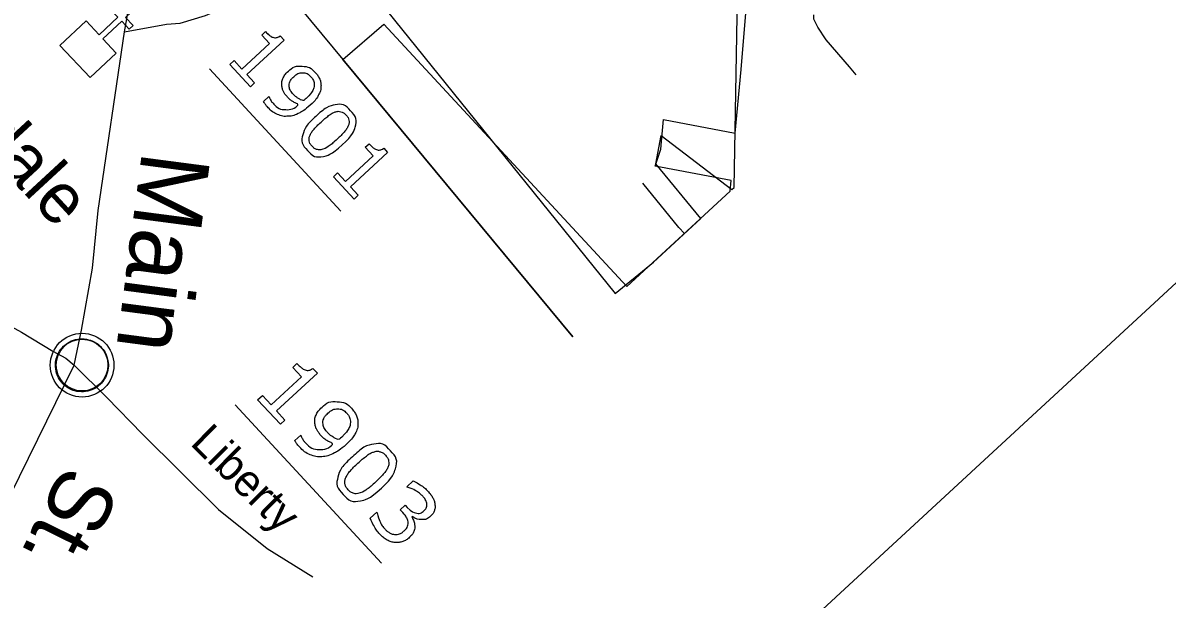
# Model space of a CAD drawing. Extents: x 1695041 to 1706254, y 786537 to 798223.
# Drawn here: x 1703274.6 to 1703431.2, y 796468.6 to 796547.5 of the extents above; entities that cross this region are included whole.
import ezdxf

# ---------------------------------------------------------------- set-up
doc = ezdxf.new("R2010")
doc.units = 0
for name, color, linetype in [('Default', 7, 'Continuous'), ('Old_Level_29', 7, 'Continuous'), ('Old_Level_32', 7, 'Continuous')]:
    doc.layers.add(name, color=color, linetype=linetype)

msp = doc.modelspace()

# ---------------------------------------------------------------- linework, layer by layer
at = {"layer": 'Default'}
for p, q in [((1703300.12, 796541.16), (1703318.09, 796521.69)), ((1703357.25, 796511.38), (1703371.39, 796524.43)), ((1703357.25, 796511.38), (1703371.39, 796524.43)), ((1703371.64, 796524.66), (1703371.94, 796524.93)), ((1703371.64, 796524.66), (1703371.94, 796524.93)), ((1703360.9, 796514.74), (1703367.37, 796520.71)), ((1703360.9, 796514.74), (1703367.37, 796520.71)), ((1703303.65, 796495.22), (1703323.66, 796473.54))]:
    msp.add_line(p, q, dxfattribs=at)
for points in [[(1703207.65, 797564.73), (1702636.99, 797037.98), (1703265.12, 796357.5), (1703835.77, 796884.26)], [(1702807.76, 797162.38), (1703001.1, 796924.8), (1703349.84, 796504.53)], [(1702807.76, 797162.38), (1703001.1, 796924.8), (1703349.84, 796504.53)], [(1703371.39, 796524.43), (1703371.52, 796525.89), (1703361.13, 796527.87), (1703361.9, 796530.18), (1703362.01, 796531.24), (1703362.28, 796534.24), (1703372.1, 796532.36), (1703372.88, 796541.09), (1703375.01, 796566.38), (1703386.35, 796574.51), (1703405.54, 796588.27), (1703399.28, 796595.84), (1703390.32, 796606.91), (1703386.08, 796612.13)], [(1703371.39, 796524.43), (1703371.52, 796525.89), (1703361.13, 796527.87), (1703361.9, 796530.18), (1703362.01, 796531.24), (1703362.28, 796534.24), (1703372.1, 796532.36), (1703372.88, 796541.09), (1703375.01, 796566.38), (1703386.35, 796574.51), (1703405.54, 796588.27), (1703399.28, 796595.84), (1703390.32, 796606.91), (1703386.08, 796612.13)], [(1703371.94, 796524.93), (1703372.66, 796566.64), (1703383.15, 796574.17)], [(1703371.94, 796524.93), (1703372.66, 796566.64), (1703383.15, 796574.17)], [(1703311.01, 796570.02), (1703306.15, 796565.77), (1703312, 796559.82), (1703306.76, 796554.78), (1703310.43, 796550.3), (1703318.36, 796556.64), (1703355.63, 796510.46), (1703360.9, 796514.74)], [(1703311.01, 796570.02), (1703306.15, 796565.77), (1703312, 796559.82), (1703306.76, 796554.78), (1703310.43, 796550.3), (1703318.36, 796556.64), (1703355.63, 796510.46), (1703360.9, 796514.74)], [(1703388.63, 796540.34), (1703387.75, 796541.43), (1703384.53, 796545.16), (1703383.38, 796546.89), (1703382.84, 796547.96), (1703382.84, 796548.56)], [(1703305.72, 796538.71), (1703302.9, 796541.77), (1703303.48, 796542.3), (1703304.56, 796541.13), (1703308.35, 796544.62), (1703307.26, 796545.8), (1703307.78, 796546.27)], [(1703349.84, 796504.53), (1703318.37, 796542.46), (1703323.96, 796547.31), (1703357.25, 796511.38)], [(1703349.84, 796504.53), (1703318.37, 796542.46), (1703323.96, 796547.31), (1703357.25, 796511.38)], [(1703309.78, 796545.68), (1703310.33, 796545.1), (1703305.24, 796540.4), (1703306.3, 796539.24), (1703305.72, 796538.71)], [(1703307.53, 796536.71), (1703308.26, 796537.38), (1703308.3, 796537.34)], [(1703367.37, 796520.71), (1703361.22, 796528.2), (1703361.93, 796532.07), (1703371.64, 796524.66)], [(1703367.37, 796520.71), (1703361.22, 796528.2), (1703361.93, 796532.07), (1703371.64, 796524.66)], [(1703319.9, 796523.36), (1703317.08, 796526.41), (1703317.65, 796526.95), (1703318.74, 796525.77), (1703322.52, 796529.26), (1703321.44, 796530.44), (1703321.96, 796530.92)], [(1703323.96, 796530.33), (1703324.5, 796529.74), (1703319.41, 796525.04), (1703320.48, 796523.89), (1703319.9, 796523.36)], [(1703365.13, 796518.65), (1703364.35, 796519.47), (1703359.45, 796525.55)], [(1703349.84, 796504.53), (1703349.84, 796504.53)], [(1703349.84, 796504.53), (1703349.84, 796504.53)], [(1703309.82, 796492.54), (1703306.71, 796495.9), (1703307.35, 796496.48), (1703308.54, 796495.19), (1703312.7, 796499.03), (1703311.51, 796500.33), (1703312.08, 796500.85)], [(1703314.28, 796500.2), (1703314.88, 796499.56), (1703309.28, 796494.39), (1703310.45, 796493.12), (1703309.82, 796492.54)], [(1703311.8, 796490.33), (1703312.61, 796491.07), (1703312.64, 796491.03)], [(1703327.16, 796483.94), (1703327.12, 796483.99), (1703327.99, 796484.79)], [(1703322.13, 796479.71), (1703323.01, 796480.52), (1703323.06, 796480.45)], [(1703326.57, 796480.46), (1703326.23, 796480.83), (1703326.92, 796481.47), (1703327.19, 796481.18)], [(1703327.86, 796479.93), (1703327.8, 796479.87)]]:
    msp.add_lwpolyline(points, dxfattribs=at)
for points in [[(1703283.23, 796547.74), (1703285.03, 796545.83), (1703287.59, 796548.23), (1703286.58, 796549.31), (1703287.12, 796549.82), (1703288.13, 796548.74), (1703290.16, 796550.64), (1703290.67, 796550.1), (1703288.64, 796548.2), (1703289.65, 796547.12), (1703289.11, 796546.61), (1703288.1, 796547.69), (1703285.53, 796545.29), (1703287.35, 796543.34), (1703283.76, 796539.98), (1703279.64, 796544.38)], [(1703280.66, 796503.65), (1703280.89, 796503.79), (1703281.16, 796503.94), (1703281.5, 796504.06), (1703281.79, 796504.14), (1703282.09, 796504.21), (1703282.38, 796504.24), (1703282.65, 796504.25), (1703282.95, 796504.23), (1703283.28, 796504.19), (1703283.57, 796504.12), (1703283.82, 796504.05), (1703284.07, 796503.95), (1703284.31, 796503.84), (1703284.55, 796503.7), (1703284.73, 796503.59), (1703284.9, 796503.45), (1703285.06, 796503.33), (1703285.27, 796503.13), (1703285.4, 796502.97), (1703285.57, 796502.77), (1703285.7, 796502.58), (1703285.82, 796502.38), (1703285.93, 796502.17), (1703286.03, 796501.93), (1703286.13, 796501.62), (1703286.21, 796501.29), (1703286.25, 796501.01), (1703286.28, 796500.71), (1703286.27, 796500.5), (1703286.25, 796500.22), (1703286.22, 796499.94), (1703286.16, 796499.7), (1703286.08, 796499.43), (1703285.99, 796499.19), (1703285.88, 796498.96), (1703285.76, 796498.75), (1703285.64, 796498.56), (1703285.47, 796498.34), (1703285.33, 796498.17), (1703285.14, 796497.97), (1703284.93, 796497.8), (1703284.72, 796497.64), (1703284.51, 796497.5), (1703284.25, 796497.36), (1703283.99, 796497.24), (1703283.75, 796497.16), (1703283.44, 796497.08), (1703283.16, 796497.02), (1703282.89, 796496.99), (1703282.6, 796496.99), (1703282.26, 796497.01), (1703281.97, 796497.05), (1703281.69, 796497.12), (1703281.47, 796497.19), (1703281.15, 796497.31), (1703280.83, 796497.47), (1703280.6, 796497.63), (1703280.35, 796497.81), (1703280.19, 796497.95), (1703280.04, 796498.09), (1703279.87, 796498.28), (1703279.75, 796498.44), (1703279.59, 796498.65), (1703279.45, 796498.9), (1703279.35, 796499.09), (1703279.26, 796499.33), (1703279.18, 796499.54), (1703279.13, 796499.75), (1703279.06, 796500.11), (1703279.03, 796500.43), (1703279.03, 796500.74), (1703279.05, 796501.04), (1703279.09, 796501.27), (1703279.13, 796501.51), (1703279.25, 796501.87), (1703279.31, 796502.04), (1703279.4, 796502.22), (1703279.59, 796502.56), (1703279.78, 796502.84), (1703279.94, 796503.02), (1703280.14, 796503.23), (1703280.3, 796503.38), (1703280.54, 796503.57)]]:
    msp.add_lwpolyline(points, close=True, dxfattribs=at)
for centre, radius in [((1703282.68, 796500.63), 4.36), ((1703282.68, 796500.64), 3.54)]:
    msp.add_circle(centre, radius, dxfattribs=at)
for points in [[(1703307.78, 796546.27), (1703308, 796546.03), (1703308.29, 796545.8), (1703308.58, 796545.56), (1703308.79, 796545.49), (1703309.05, 796545.4), (1703309.28, 796545.44), (1703309.52, 796545.47), (1703309.78, 796545.68)], [(1703308.3, 796537.34), (1703308.34, 796537.18), (1703308.47, 796536.93), (1703308.61, 796536.68), (1703308.83, 796536.44), (1703309.61, 796535.6), (1703310.55, 796535.59), (1703311.49, 796535.58), (1703312.44, 796536.32), (1703311.91, 796536.47), (1703311.53, 796536.7), (1703311.15, 796536.92), (1703310.81, 796537.29), (1703310.49, 796537.64), (1703310.3, 796537.99), (1703310.1, 796538.33), (1703310.04, 796538.8), (1703309.96, 796539.34), (1703310.17, 796539.84), (1703310.37, 796540.34), (1703310.86, 796540.8), (1703311.73, 796541.6), (1703312.8, 796541.53), (1703313.87, 796541.46), (1703314.62, 796540.65), (1703315, 796540.24), (1703315.2, 796539.77), (1703315.39, 796539.3), (1703315.38, 796538.81), (1703315.36, 796538.19), (1703315.03, 796537.56), (1703314.69, 796536.93), (1703313.91, 796536.2)], [(1703313.36, 796537.13), (1703313.95, 796537.67), (1703314.19, 796538.12), (1703314.44, 796538.57), (1703314.44, 796538.96), (1703314.45, 796539.3), (1703314.33, 796539.57), (1703314.22, 796539.85), (1703314, 796540.08), (1703313.49, 796540.63), (1703312.86, 796540.63), (1703312.23, 796540.63), (1703311.61, 796540.06), (1703311.25, 796539.73), (1703311.11, 796539.42), (1703310.98, 796539.1), (1703311.03, 796538.7), (1703311.07, 796538.42), (1703311.22, 796538.18), (1703311.37, 796537.94), (1703311.6, 796537.69), (1703311.87, 796537.4), (1703312.23, 796537.17), (1703312.59, 796536.94), (1703312.99, 796536.81), (1703313.07, 796536.88), (1703313.16, 796536.95), (1703313.24, 796537.01), (1703313.36, 796537.13)], [(1703313.91, 796536.2), (1703313.16, 796535.52), (1703312.41, 796535.13), (1703311.65, 796534.74), (1703310.9, 796534.69), (1703310.15, 796534.64), (1703309.44, 796534.94), (1703308.72, 796535.24), (1703308.07, 796535.94), (1703307.89, 796536.14), (1703307.75, 796536.34), (1703307.61, 796536.53), (1703307.53, 796536.71)], [(1703318.29, 796530.77), (1703316.77, 796529.37), (1703315.62, 796529.18), (1703314.47, 796529), (1703313.54, 796530), (1703312.6, 796531.02), (1703312.89, 796532.15), (1703313.18, 796533.29), (1703314.68, 796534.67), (1703316.19, 796536.06), (1703317.34, 796536.25), (1703318.5, 796536.44), (1703319.43, 796535.44), (1703320.37, 796534.42), (1703320.07, 796533.28), (1703319.77, 796532.14), (1703318.29, 796530.77)], [(1703315.65, 796530.18), (1703316.08, 796530.33), (1703316.54, 796530.67), (1703317, 796531), (1703317.58, 796531.54), (1703318.16, 796532.08), (1703318.54, 796532.52), (1703318.92, 796532.96), (1703319.09, 796533.37), (1703319.26, 796533.77), (1703319.2, 796534.13), (1703319.13, 796534.5), (1703318.8, 796534.86), (1703318.47, 796535.22), (1703318.11, 796535.31), (1703317.75, 796535.41), (1703317.32, 796535.27), (1703316.92, 796535.14), (1703316.42, 796534.77), (1703315.93, 796534.4), (1703315.39, 796533.9), (1703314.8, 796533.35), (1703314.44, 796532.94), (1703314.08, 796532.53), (1703313.89, 796532.11), (1703313.71, 796531.71), (1703313.76, 796531.33), (1703313.82, 796530.96), (1703314.17, 796530.58), (1703314.5, 796530.23), (1703314.86, 796530.13), (1703315.23, 796530.03), (1703315.65, 796530.18)], [(1703321.96, 796530.92), (1703322.18, 796530.68), (1703322.47, 796530.44), (1703322.76, 796530.2), (1703322.97, 796530.13), (1703323.22, 796530.05), (1703323.46, 796530.08), (1703323.7, 796530.12), (1703323.96, 796530.33)], [(1703312.08, 796500.85), (1703312.32, 796500.59), (1703312.64, 796500.33), (1703312.96, 796500.07), (1703313.19, 796499.99), (1703313.47, 796499.9), (1703313.73, 796499.93), (1703314, 796499.97), (1703314.28, 796500.2)], [(1703312.64, 796491.03), (1703312.69, 796490.85), (1703312.84, 796490.58), (1703312.99, 796490.3), (1703313.24, 796490.03), (1703314.09, 796489.11), (1703315.12, 796489.1), (1703316.16, 796489.08), (1703317.21, 796489.9), (1703316.62, 796490.07), (1703316.2, 796490.32), (1703315.78, 796490.57), (1703315.41, 796490.97), (1703315.06, 796491.36), (1703314.85, 796491.74), (1703314.63, 796492.12), (1703314.56, 796492.63), (1703314.48, 796493.23), (1703314.7, 796493.78), (1703314.92, 796494.33), (1703315.47, 796494.83), (1703316.42, 796495.71), (1703317.6, 796495.64), (1703318.77, 796495.56), (1703319.61, 796494.66), (1703320.02, 796494.21), (1703320.24, 796493.7), (1703320.45, 796493.18), (1703320.44, 796492.64), (1703320.42, 796491.96), (1703320.05, 796491.27), (1703319.68, 796490.57), (1703318.82, 796489.78)], [(1703318.22, 796490.79), (1703318.86, 796491.39), (1703319.13, 796491.88), (1703319.4, 796492.38), (1703319.4, 796492.81), (1703319.41, 796493.18), (1703319.28, 796493.48), (1703319.16, 796493.78), (1703318.92, 796494.04), (1703318.36, 796494.64), (1703317.67, 796494.64), (1703316.97, 796494.65), (1703316.29, 796494.02), (1703315.89, 796493.65), (1703315.75, 796493.31), (1703315.6, 796492.96), (1703315.66, 796492.53), (1703315.7, 796492.22), (1703315.86, 796491.95), (1703316.03, 796491.69), (1703316.28, 796491.41), (1703316.58, 796491.09), (1703316.98, 796490.84), (1703317.37, 796490.58), (1703317.81, 796490.45), (1703317.9, 796490.52), (1703317.99, 796490.59), (1703318.08, 796490.67), (1703318.22, 796490.79)], [(1703318.82, 796489.78), (1703318, 796489.02), (1703317.17, 796488.6), (1703316.33, 796488.17), (1703315.51, 796488.11), (1703314.69, 796488.05), (1703313.9, 796488.39), (1703313.11, 796488.72), (1703312.4, 796489.49), (1703312.2, 796489.71), (1703312.05, 796489.92), (1703311.89, 796490.13), (1703311.8, 796490.33)], [(1703323.64, 796483.8), (1703321.96, 796482.25), (1703320.7, 796482.05), (1703319.43, 796481.85), (1703318.42, 796482.96), (1703317.38, 796484.07), (1703317.7, 796485.32), (1703318.02, 796486.57), (1703319.67, 796488.09), (1703321.33, 796489.62), (1703322.6, 796489.83), (1703323.87, 796490.04), (1703324.89, 796488.93), (1703325.92, 796487.82), (1703325.59, 796486.56), (1703325.27, 796485.3), (1703323.64, 796483.8)], [(1703320.73, 796483.15), (1703321.2, 796483.31), (1703321.71, 796483.68), (1703322.21, 796484.05), (1703322.86, 796484.65), (1703323.49, 796485.23), (1703323.91, 796485.72), (1703324.33, 796486.2), (1703324.52, 796486.65), (1703324.71, 796487.1), (1703324.64, 796487.5), (1703324.57, 796487.9), (1703324.2, 796488.3), (1703323.84, 796488.69), (1703323.44, 796488.8), (1703323.04, 796488.9), (1703322.57, 796488.75), (1703322.13, 796488.6), (1703321.59, 796488.2), (1703321.04, 796487.79), (1703320.45, 796487.24), (1703319.8, 796486.64), (1703319.4, 796486.19), (1703319, 796485.74), (1703318.8, 796485.27), (1703318.6, 796484.83), (1703318.66, 796484.42), (1703318.72, 796484.01), (1703319.1, 796483.59), (1703319.47, 796483.2), (1703319.87, 796483.09), (1703320.27, 796482.98), (1703320.73, 796483.15)], [(1703327.99, 796484.79), (1703328.41, 796484.63), (1703328.99, 796484.25), (1703329.57, 796483.87), (1703330, 796483.4), (1703330.42, 796482.95), (1703330.66, 796482.52), (1703330.89, 796482.1), (1703330.97, 796481.65), (1703331.04, 796481.16), (1703330.9, 796480.75), (1703330.76, 796480.33), (1703330.38, 796479.98), (1703329.86, 796479.5), (1703329.14, 796479.51), (1703328.42, 796479.52), (1703327.86, 796479.93)], [(1703327.19, 796481.18), (1703327.77, 796480.54), (1703328.39, 796480.41), (1703329, 796480.28), (1703329.51, 796480.75), (1703329.74, 796480.95), (1703329.82, 796481.21), (1703329.9, 796481.46), (1703329.85, 796481.73), (1703329.79, 796482.01), (1703329.65, 796482.25), (1703329.5, 796482.5), (1703329.26, 796482.76), (1703328.89, 796483.15), (1703328.34, 796483.47), (1703327.78, 796483.79), (1703327.16, 796483.94)], [(1703323.06, 796480.45), (1703323.16, 796479.88), (1703323.45, 796479.26), (1703323.73, 796478.64), (1703324.15, 796478.19), (1703324.39, 796477.93), (1703324.75, 796477.71), (1703325.11, 796477.5), (1703325.46, 796477.47), (1703325.82, 796477.45), (1703326.13, 796477.56), (1703326.43, 796477.67), (1703326.77, 796477.98), (1703327.11, 796478.29), (1703327.23, 796478.6), (1703327.35, 796478.91), (1703327.3, 796479.21), (1703327.26, 796479.52), (1703327.06, 796479.83), (1703326.86, 796480.15), (1703326.57, 796480.46)], [(1703328.22, 796478.6), (1703328.23, 796478.23), (1703328.07, 796477.85), (1703327.92, 796477.48), (1703327.49, 796477.08), (1703327.07, 796476.68), (1703326.57, 796476.51), (1703326.07, 796476.34), (1703325.55, 796476.37), (1703324.97, 796476.42), (1703324.44, 796476.71), (1703323.91, 796477.01), (1703323.44, 796477.51), (1703322.96, 796478.03), (1703322.62, 796478.64), (1703322.28, 796479.26), (1703322.13, 796479.71)], [(1703327.8, 796479.87), (1703327.95, 796479.64), (1703328.08, 796479.28), (1703328.21, 796478.93), (1703328.22, 796478.6)]]:
    msp.add_open_spline(points, degree=3, dxfattribs=at)
at = {"layer": 'Old_Level_29'}
for points in [[(1703288.47, 796546.24), (1703288.81, 796548.02), (1703290.57, 796559.6), (1703292.44, 796573.7)], [(1703281.6, 796500.65), (1703282.61, 796505.44), (1703284.12, 796513.9), (1703284.88, 796521.79), (1703288.47, 796546.24)], [(1703225.93, 796532.29), (1703240.58, 796524.02), (1703256.49, 796515.14), (1703263.88, 796510.91), (1703274.38, 796505.16), (1703278.66, 796502.54), (1703280.45, 796501.59), (1703281.6, 796500.65)], [(1703250.98, 796413.28), (1703251.07, 796415.22), (1703253.92, 796427.16), (1703260.64, 796453.43), (1703262.54, 796460.04), (1703269.59, 796476.25), (1703270.32, 796477.78), (1703281.6, 796500.65)], [(1703281.6, 796500.65), (1703286.06, 796496.23), (1703290.94, 796491.19), (1703301.37, 796480.87), (1703307.99, 796475.56), (1703314.24, 796471.68)]]:
    msp.add_lwpolyline(points, dxfattribs=at)
at = {"layer": 'Old_Level_32'}
msp.add_lwpolyline([(1703288.47, 796546.24), (1703294.23, 796547.27), (1703296.1, 796547.44), (1703299.56, 796548.47), (1703301.31, 796549.2), (1703305.53, 796550.72), (1703308.02, 796551.8), (1703309.65, 796552.97)], dxfattribs=at)

# ---------------------------------------------------------------- texts
at = {"layer": 'Default'}
for s, height, rotation, p in [('Archdale', 6.93, 312.7091, (1703254.51, 796545.99)), ('Main', 9.408, 262.5279, (1703290.91, 796530.1)), ('Liberty', 4.389, 315.2603, (1703297.32, 796489.84)), ('St.', 8.553, 243.7049, (1703280.32, 796487.31))]:
    msp.add_text(s, height=height, rotation=rotation, dxfattribs=at).set_placement(p)

doc.saveas('drawing.dxf')
